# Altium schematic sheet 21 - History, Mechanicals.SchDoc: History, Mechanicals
size A3; PageSetup: Record=PageOptions¦CenterHorizontal=True¦CenterVertical=True¦PrintScale=1.01¦XCorrection=1.00¦YCorrection=1.00¦PrintKind=0¦BorderSize=5000000¦LeftOffset=0¦BottomOffset=0¦Orientation=2¦PaperLength=4200¦PaperWidth=2970¦Scale=100¦PaperSource=15¦PrintQuality=600¦MediaType=1¦DitherType=10¦PrintScaleMode=1¦PaperKind=A3¦PaperIndex=8; Author: Juan Anzola; SheetNumber: 21; SheetTotal: 21
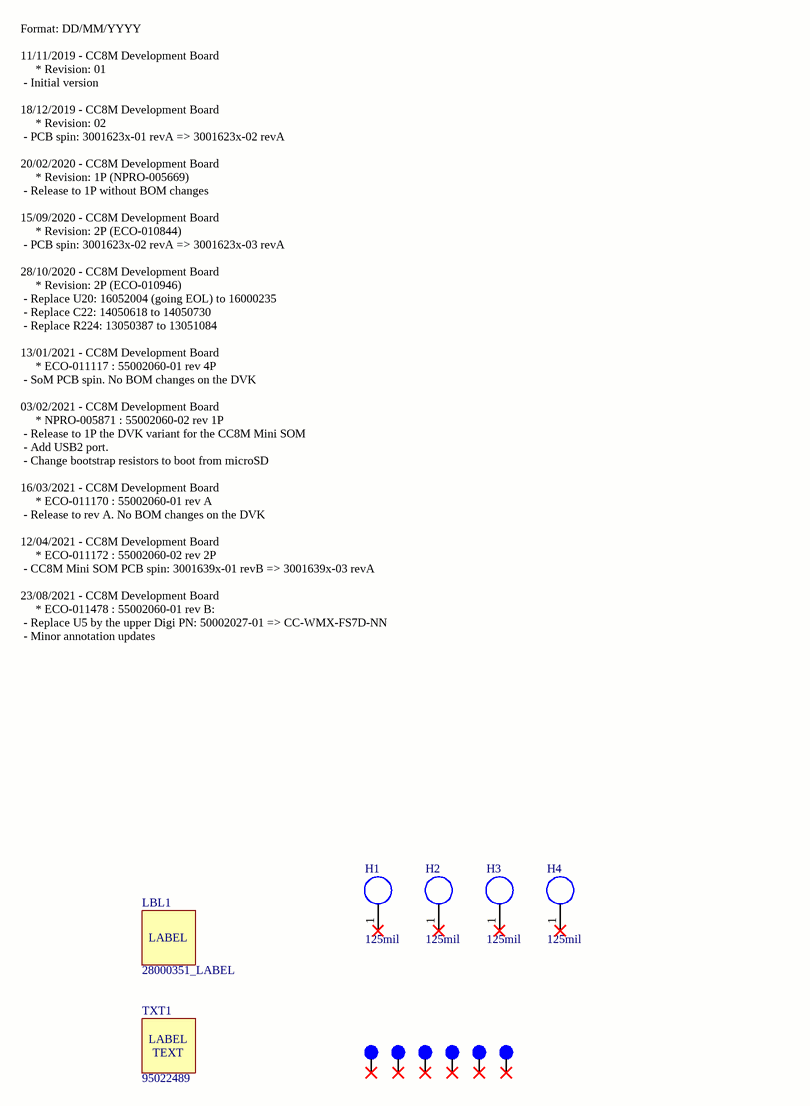
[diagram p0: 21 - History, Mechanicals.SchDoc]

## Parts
FIDUCIAL1  40mil FID  [fiducial_40mil_round]  (value not drawn)  (no BOM)
FIDUCIAL2  40mil FID  [fiducial_40mil_round]  (value not drawn)  (no BOM)
FIDUCIAL3  40mil FID  [fiducial_40mil_round]  (value not drawn)  (no BOM)
FIDUCIAL4  40mil FID  [fiducial_40mil_round]  (value not drawn)  (no BOM)
FIDUCIAL5  40mil FID  [fiducial_40mil_round]  (value not drawn)  (no BOM)
FIDUCIAL6  40mil FID  [fiducial_40mil_round]  (value not drawn)  (no BOM)
H1  125mil  [MH_185_125_NP]  (no BOM)
H2  125mil  [MH_185_125_NP]  (no BOM)
H3  125mil  [MH_185_125_NP]  (no BOM)
H4  125mil  [MH_185_125_NP]  (no BOM)
LBL1  28000351_LABEL
TXT1  95022489  (mechanical)

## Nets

Not connected (* = marked no-connect by the designer): FIDUCIAL1 1(Fid_1)*; FIDUCIAL2 1(Fid_1)*; FIDUCIAL3 1(Fid_1)*; FIDUCIAL4 1(Fid_1)*; FIDUCIAL5 1(Fid_1)*; FIDUCIAL6 1(Fid_1)*; H1 1(TOOL)*; H2 1(TOOL)*; H3 1(TOOL)*; H4 1(TOOL)*

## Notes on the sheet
- Format: DD/MM/YYYY
  11/11/2019 - CC8M Development Board
  * Revision: 01
  - Initial version
  18/12/2019 - CC8M Development Board
  * Revision: 02
  - PCB spin: 3001623x-01 revA => 3001623x-02 revA
  20/02/2020 - CC8M Development Board
  * Revision: 1P (NPRO-005669)
  - Release to 1P without BOM changes
  15/09/2020 - CC8M Development Board
  * Revision: 2P (ECO-010844)
  - PCB spin: 3001623x-02 revA => 3001623x-03 revA
  28/10/2020 - CC8M Development Board
  * Revision: 2P (ECO-010946)
  - Replace U20: 16052004 (going EOL) to 16000235
  - Replace C22: 14050618 to 14050730
  - Replace R224: 13050387 to 13051084
  13/01/2021 - CC8M Development Board
  * ECO-011117 : 55002060-01 rev 4P
  - SoM PCB spin. No BOM changes on the DVK
  03/02/2021 - CC8M Development Board
  * NPRO-005871 : 55002060-02 rev 1P
  - Release to 1P the DVK variant for the CC8M Mini SOM
  - Add USB2 port.
  - Change bootstrap resistors to boot from microSD
  16/03/2021 - CC8M Development Board
  * ECO-011170 : 55002060-01 rev A
  - Release to rev A. No BOM changes on the DVK
  12/04/2021 - CC8M Development Board
  * ECO-011172 : 55002060-02 rev 2P
  - CC8M Mini SOM PCB spin: 3001639x-01 revB => 3001639x-03 revA
  23/08/2021 - CC8M Development Board
  * ECO-011478 : 55002060-01 rev B:
  - Replace U5 by the upper Digi PN: 50002027-01 => CC-WMX-FS7D-NN
  - Minor annotation updates

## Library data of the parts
FIDUCIAL1-FIDUCIAL6 = CAD0023: 40 Mil Round Fiducial; Part_Type: Mechanical; Component_Life_Cycle_State: Reviewed; Area: 1; Project: SDR Prototype RF Board
H1-H4 = CAD0006: NPTH for Tooling, 0.125in dia.; Part_Type: Mechanical; Component_Life_Cycle_State: Proven; Area: 0.98; Project: Adjustable Foundation
LBL1 = 1002170: LBL,Poly White Blank 0.40x0.40; Manufacturer: 3M; Manufacturer_Part_Number: TAAE-014000; Noplace: False; Component_Life_Cycle_State: Created; Area: 100; Project: CCWMX6_SBC board
TXT1 = CAD0102: Text,.5x.75" 55002060-01 IMX8MN (DVK); Part_Type: Label; Noplace: False; Note: CAD ONLY; Component_Life_Cycle_State: Pending; Area: 0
